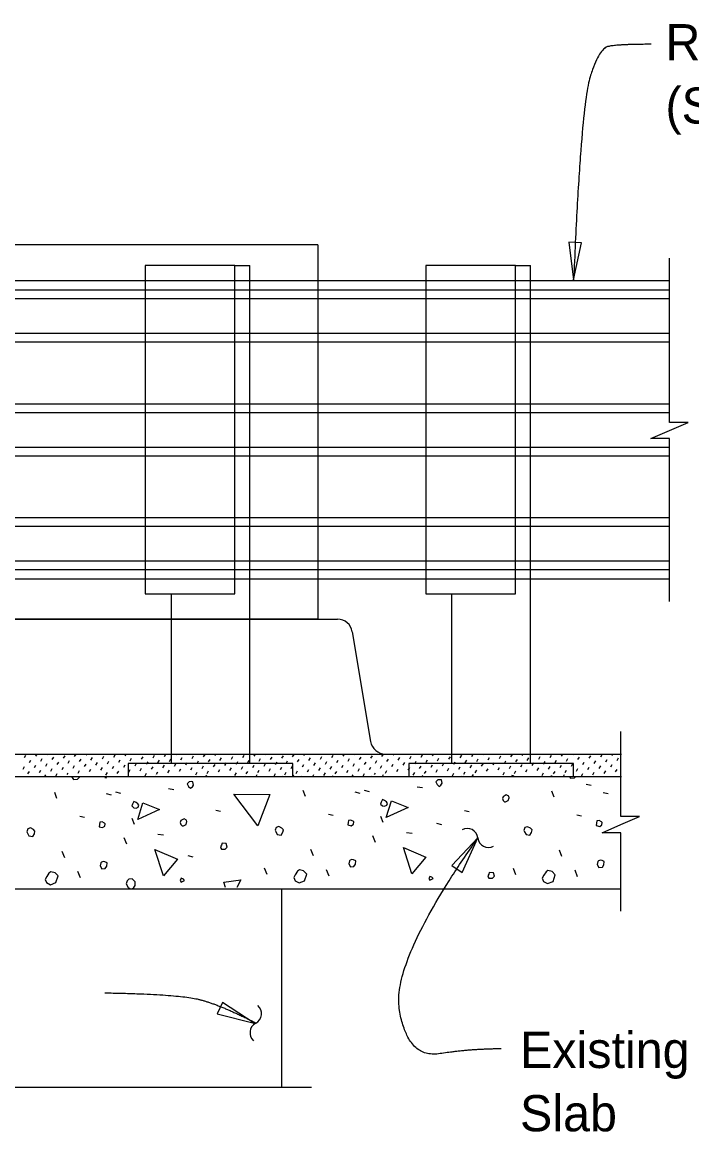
# Model space of a CAD drawing. Extents: x 0 to 41.1, y 0 to 25.9.
# Drawn here: x 16.72 to 20.45, y 6.25 to 12.42 of the extents above; entities that cross this region are included whole.
import ezdxf

# ---------------------------------------------------------------- set-up
doc = ezdxf.new("R2010")
doc.units = 0
for name, color, linetype in [('Dimension', 7, 'Continuous'), ('Miscellaneous', 7, 'Continuous'), ('TrafBarrierConc', 7, 'Continuous')]:
    doc.layers.add(name, color=color, linetype=linetype)

msp = doc.modelspace()

# ---------------------------------------------------------------- linework, layer by layer
at = {"layer": 'Dimension'}
for points in [[(19.789, 10.9864), (19.8331, 11.193), (19.7626, 11.196)], [(19.2567, 7.882), (19.1108, 7.7292), (19.1693, 7.6897)], [(18.0103, 6.8509), (17.8341, 6.9674), (17.8055, 6.9029)]]:
    msp.add_lwpolyline(points, close=True, dxfattribs=at)
for points in [[(20.3226, 9.1983), (20.3226, 10.1038), (20.2193, 10.1038), (20.3226, 10.1488), (20.426, 10.1938), (20.3226, 10.1938), (20.3226, 11.1084)], [(20.0523, 7.4738), (20.0523, 7.9111), (19.9489, 7.9111), (20.0523, 7.9561), (20.1556, 8.0011), (20.0523, 8.0011), (20.0523, 8.4739)], [(18.3306, 6.4942), (16.3423, 6.4942), (16.3423, 6.3779), (16.243, 6.6029), (16.243, 6.4942), (14.7437, 6.4942)]]:
    msp.add_lwpolyline(points, dxfattribs=at)
for centre, start, end in [((19.1968, 7.8756), 6.49806, 118.22528), ((19.3153, 7.8891), 186.49806, 298.22528), ((17.9922, 6.9044), 297.39149, 49.11871), ((18.047, 6.7985), 117.39149, 229.11871)]:
    msp.add_arc(centre, 0.0596, start, end, dxfattribs=at)
for points in [[(20.2213, 12.2973), (20.0218, 12.2973), (19.9303, 12.2696), (19.8306, 11.9592), (19.789, 10.9864)], [(19.3858, 6.7084), (19.2176, 6.7084), (18.8649, 6.655), (18.774, 7.1974), (19.2561, 7.8825)], [(17.1798, 7.0204), (17.5907, 7.013), (17.8234, 6.9532), (18.0193, 6.8535)]]:
    msp.add_open_spline(points, degree=2, dxfattribs=at)
at = {"layer": 'Miscellaneous'}
for p, q in [((17.9041, 11.0667), (17.9874, 11.0667)), ((17.9873, 8.2968), (17.9873, 11.0667)), ((19.4661, 11.0667), (19.5493, 11.0667)), ((19.5493, 8.2968), (19.5493, 11.0667)), ((11.0597, 10.9834), (20.3226, 10.9834)), ((11.7173, 10.9312), (20.3226, 10.9312)), ((11.7186, 10.8829), (20.3226, 10.8829)), ((11.7232, 10.6901), (20.3226, 10.6901)), ((11.7244, 10.6419), (20.3226, 10.6419)), ((11.7197, 10.2497), (20.3226, 10.2497)), ((11.721, 10.2979), (20.3226, 10.2979)), ((11.7103, 10.0088), (20.3226, 10.0088)), ((11.7145, 10.0569), (20.3226, 10.0569)), ((11.7244, 9.6648), (20.3226, 9.6648)), ((11.7232, 9.6166), (20.3226, 9.6166)), ((11.717, 9.4238), (20.3226, 9.4238)), ((11.0597, 9.3233), (20.3226, 9.3233)), ((11.718, 9.3755), (20.3226, 9.3755)), ((17.55, 8.2968), (17.55, 9.2399)), ((19.112, 8.2968), (19.112, 9.2399)), ((16.7325, 8.3291), (16.7406, 8.3431)), ((16.7959, 8.3372), (16.8027, 8.3489)), ((16.8594, 8.3453), (16.8615, 8.3489)), ((16.9506, 8.3257), (16.9587, 8.3397)), ((17.0115, 8.3345), (17.0196, 8.3485)), ((17.075, 8.3426), (17.0787, 8.3489)), ((17.1662, 8.323), (17.1743, 8.337)), ((17.2297, 8.3311), (17.2378, 8.3451)), ((17.2932, 8.3392), (17.2988, 8.3489)), ((17.3567, 8.3473), (17.3576, 8.3489)), ((17.4479, 8.3277), (17.456, 8.3417)), ((17.5114, 8.3358), (17.5189, 8.3489)), ((17.5749, 8.344), (17.5777, 8.3489)), ((17.6661, 8.3244), (17.6742, 8.3384)), ((17.7295, 8.3325), (17.7376, 8.3465)), ((17.793, 8.3406), (17.7979, 8.3489)), ((17.8565, 8.3487), (17.8567, 8.3489)), ((17.8842, 8.321), (17.8923, 8.335)), ((17.9477, 8.3291), (17.9558, 8.3431)), ((18.0112, 8.3372), (18.018, 8.3489)), ((18.0747, 8.3453), (18.0768, 8.3489)), ((18.1659, 8.3257), (18.174, 8.3397)), ((18.2248, 8.3325), (18.2329, 8.3465)), ((18.2883, 8.3406), (18.2931, 8.3489)), ((18.3518, 8.3487), (18.3519, 8.3489)), ((18.3795, 8.321), (18.3876, 8.335)), ((18.443, 8.3291), (18.4511, 8.3431)), ((18.5065, 8.3372), (18.5133, 8.3489)), ((18.57, 8.3453), (18.5721, 8.3489)), ((18.6612, 8.3257), (18.6693, 8.3397)), ((18.7221, 8.3345), (18.7302, 8.3485)), ((18.7856, 8.3426), (18.7892, 8.3489)), ((18.8767, 8.323), (18.8848, 8.337)), ((18.9402, 8.3311), (18.9483, 8.3451)), ((19.0037, 8.3392), (19.0093, 8.3489)), ((19.0672, 8.3473), (19.0681, 8.3489)), ((19.1584, 8.3277), (19.1665, 8.3417)), ((19.2219, 8.3358), (19.2295, 8.3489)), ((19.2854, 8.344), (19.2883, 8.3489)), ((19.3766, 8.3244), (19.3847, 8.3384)), ((19.4401, 8.3325), (19.4482, 8.3465)), ((19.5036, 8.3406), (19.5084, 8.3489)), ((19.5671, 8.3487), (19.5672, 8.3489)), ((19.5947, 8.321), (19.6028, 8.335)), ((19.6582, 8.3291), (19.6663, 8.3431)), ((19.7217, 8.3372), (19.7285, 8.3489)), ((19.7852, 8.3453), (19.7873, 8.3489)), ((19.8764, 8.3257), (19.8845, 8.3397)), ((19.94, 8.3325), (19.9481, 8.3465)), ((20.0035, 8.3406), (20.0083, 8.3489)), ((16.7244, 8.2656), (16.7325, 8.2796)), ((16.7602, 8.3014), (16.7683, 8.3154)), ((16.7878, 8.2737), (16.7959, 8.2877)), ((16.8236, 8.3095), (16.8317, 8.3235)), ((16.8513, 8.2818), (16.8594, 8.2958)), ((16.8871, 8.3176), (16.8952, 8.3316)), ((16.9148, 8.2899), (16.9229, 8.3039)), ((16.9425, 8.2622), (16.9506, 8.2762)), ((16.9757, 8.2987), (16.9838, 8.3127)), ((17.0034, 8.271), (17.0115, 8.285)), ((17.0392, 8.3068), (17.0473, 8.3208)), ((17.0669, 8.2791), (17.075, 8.2931)), ((17.1027, 8.3149), (17.1108, 8.3289)), ((17.1304, 8.2872), (17.1385, 8.3012)), ((17.1581, 8.2595), (17.1662, 8.2735)), ((17.1939, 8.2953), (17.202, 8.3093)), ((17.2216, 8.2676), (17.2297, 8.2816)), ((17.2574, 8.3034), (17.2655, 8.3174)), ((17.2851, 8.2757), (17.2932, 8.2897)), ((17.3209, 8.3115), (17.329, 8.3255)), ((17.3486, 8.2838), (17.3567, 8.2978)), ((17.3844, 8.3196), (17.3925, 8.3336)), ((17.4121, 8.2919), (17.4202, 8.3059)), ((17.4398, 8.2643), (17.4479, 8.2782)), ((17.4756, 8.3001), (17.4837, 8.314)), ((17.5033, 8.2724), (17.5114, 8.2864)), ((17.5391, 8.3082), (17.5472, 8.3221)), ((17.5668, 8.2805), (17.5749, 8.2945)), ((17.6026, 8.3163), (17.6107, 8.3303)), ((17.6303, 8.2886), (17.6384, 8.3026)), ((17.658, 8.2609), (17.6661, 8.2749)), ((17.6937, 8.2967), (17.7019, 8.3107)), ((17.7214, 8.269), (17.7295, 8.283)), ((17.7572, 8.3048), (17.7653, 8.3188)), ((17.7849, 8.2771), (17.793, 8.2911)), ((17.8207, 8.3129), (17.8288, 8.3269)), ((17.8484, 8.2852), (17.8565, 8.2992)), ((17.9119, 8.2933), (17.92, 8.3073)), ((17.9396, 8.2656), (17.9477, 8.2796)), ((17.9754, 8.3014), (17.9835, 8.3154)), ((18.0031, 8.2737), (18.0112, 8.2877)), ((18.0389, 8.3095), (18.047, 8.3235)), ((18.0666, 8.2818), (18.0747, 8.2958)), ((18.1024, 8.3176), (18.1105, 8.3316)), ((18.1301, 8.2899), (18.1382, 8.3039)), ((18.1578, 8.2622), (18.1659, 8.2762)), ((18.189, 8.2967), (18.1971, 8.3107)), ((18.2167, 8.269), (18.2248, 8.283)), ((18.2525, 8.3048), (18.2606, 8.3188)), ((18.2802, 8.2771), (18.2883, 8.2911)), ((18.316, 8.3129), (18.3241, 8.3269)), ((18.3437, 8.2852), (18.3518, 8.2992)), ((18.4072, 8.2933), (18.4153, 8.3073)), ((18.4349, 8.2656), (18.443, 8.2796)), ((18.4707, 8.3014), (18.4788, 8.3154)), ((18.4984, 8.2737), (18.5065, 8.2877)), ((18.5342, 8.3095), (18.5423, 8.3235)), ((18.5619, 8.2818), (18.57, 8.2958)), ((18.5977, 8.3176), (18.6058, 8.3316)), ((18.6254, 8.2899), (18.6335, 8.3039)), ((18.653, 8.2622), (18.6612, 8.2762)), ((18.6863, 8.2987), (18.6944, 8.3127)), ((18.714, 8.271), (18.7221, 8.285)), ((18.7498, 8.3068), (18.7579, 8.3208)), ((18.7774, 8.2791), (18.7856, 8.2931)), ((18.8132, 8.3149), (18.8213, 8.3289)), ((18.8409, 8.2872), (18.849, 8.3012)), ((18.8686, 8.2595), (18.8767, 8.2735)), ((18.9044, 8.2953), (18.9125, 8.3093)), ((18.9321, 8.2676), (18.9402, 8.2816)), ((18.9679, 8.3034), (18.976, 8.3174)), ((18.9956, 8.2757), (19.0037, 8.2897)), ((19.0314, 8.3115), (19.0395, 8.3255)), ((19.0591, 8.2838), (19.0672, 8.2978)), ((19.0949, 8.3196), (19.103, 8.3336)), ((19.1226, 8.2919), (19.1307, 8.3059)), ((19.1503, 8.2643), (19.1584, 8.2782)), ((19.1861, 8.3001), (19.1942, 8.314)), ((19.2138, 8.2724), (19.2219, 8.2864)), ((19.2496, 8.3082), (19.2577, 8.3221)), ((19.2773, 8.2805), (19.2854, 8.2945)), ((19.3131, 8.3163), (19.3212, 8.3303)), ((19.3408, 8.2886), (19.3489, 8.3026)), ((19.3685, 8.2609), (19.3766, 8.2749)), ((19.4043, 8.2967), (19.4124, 8.3107)), ((19.432, 8.269), (19.4401, 8.283)), ((19.4678, 8.3048), (19.4759, 8.3188)), ((19.4955, 8.2771), (19.5036, 8.2911)), ((19.5313, 8.3129), (19.5394, 8.3269)), ((19.5589, 8.2852), (19.5671, 8.2992)), ((19.6224, 8.2933), (19.6305, 8.3073)), ((19.6501, 8.2656), (19.6582, 8.2796)), ((19.6859, 8.3014), (19.694, 8.3154)), ((19.7136, 8.2737), (19.7217, 8.2877)), ((19.7494, 8.3095), (19.7575, 8.3235)), ((19.7771, 8.2818), (19.7852, 8.2958)), ((19.8129, 8.3176), (19.821, 8.3316)), ((19.8406, 8.2899), (19.8487, 8.3039)), ((19.8683, 8.2622), (19.8764, 8.2762)), ((19.9042, 8.2967), (19.9123, 8.3107)), ((19.9319, 8.269), (19.94, 8.283)), ((19.9677, 8.3048), (19.9758, 8.3188)), ((19.9954, 8.2771), (20.0035, 8.2911)), ((20.0312, 8.3129), (20.0393, 8.3269)), ((16.752, 8.2379), (16.7602, 8.2519)), ((16.7877, 8.2239), (16.7878, 8.2242)), ((16.8155, 8.246), (16.8236, 8.26)), ((16.8465, 8.2239), (16.8513, 8.2323)), ((16.879, 8.2541), (16.8871, 8.2681)), ((16.9067, 8.2264), (16.9148, 8.2404)), ((16.9702, 8.2345), (16.9753, 8.2432)), ((17.0311, 8.2433), (17.0392, 8.2573)), ((17.0946, 8.2514), (17.1027, 8.2654)), ((17.1858, 8.2318), (17.1939, 8.2458)), ((17.2493, 8.2399), (17.2574, 8.2539)), ((17.3128, 8.248), (17.3209, 8.262)), ((17.3763, 8.2562), (17.3844, 8.2701)), ((17.404, 8.2285), (17.4121, 8.2425)), ((17.4636, 8.2239), (17.4649, 8.2262)), ((17.4675, 8.2366), (17.4756, 8.2506)), ((17.531, 8.2447), (17.5391, 8.2587)), ((17.5945, 8.2528), (17.6026, 8.2668)), ((17.6856, 8.2332), (17.6937, 8.2472)), ((17.7425, 8.2239), (17.7466, 8.231)), ((17.7491, 8.2413), (17.7572, 8.2553)), ((17.8126, 8.2494), (17.8207, 8.2634)), ((17.8761, 8.2575), (17.8842, 8.2715)), ((17.9038, 8.2298), (17.9119, 8.2438)), ((17.9626, 8.2239), (17.9647, 8.2276)), ((17.9673, 8.2379), (17.9754, 8.2519)), ((18.0214, 8.2239), (18.0282, 8.2357)), ((18.0308, 8.246), (18.0389, 8.26)), ((18.0943, 8.2541), (18.1024, 8.2681)), ((18.122, 8.2264), (18.1301, 8.2404)), ((18.1673, 8.2239), (18.168, 8.2251)), ((18.1809, 8.2332), (18.189, 8.2472)), ((18.2261, 8.2239), (18.2315, 8.2332)), ((18.2444, 8.2413), (18.2525, 8.2553)), ((18.2781, 8.2239), (18.2802, 8.2276)), ((18.3079, 8.2494), (18.316, 8.2634)), ((18.3369, 8.2239), (18.3437, 8.2357)), ((18.3714, 8.2575), (18.3795, 8.2715)), ((18.3991, 8.2298), (18.4072, 8.2438)), ((18.4463, 8.2239), (18.4497, 8.2298)), ((18.4626, 8.2379), (18.4707, 8.2519)), ((18.4982, 8.2239), (18.4984, 8.2242)), ((18.5261, 8.246), (18.5342, 8.26)), ((18.557, 8.2239), (18.5619, 8.2323)), ((18.5896, 8.2541), (18.5977, 8.2681)), ((18.6173, 8.2264), (18.6254, 8.2404)), ((18.6664, 8.2239), (18.6678, 8.2264)), ((18.6807, 8.2345), (18.6858, 8.2432)), ((18.7252, 8.2239), (18.7313, 8.2345)), ((18.7417, 8.2433), (18.7498, 8.2573)), ((18.8051, 8.2514), (18.8132, 8.2654)), ((18.8963, 8.2318), (18.9044, 8.2458)), ((18.9453, 8.2239), (18.9495, 8.2311)), ((18.9598, 8.2399), (18.9679, 8.2539)), ((19.0233, 8.248), (19.0314, 8.262)), ((19.0868, 8.2562), (19.0949, 8.2701)), ((19.1145, 8.2285), (19.1226, 8.2425)), ((19.1655, 8.2239), (19.1677, 8.2277)), ((19.1741, 8.2239), (19.1754, 8.2262)), ((19.178, 8.2366), (19.1861, 8.2506)), ((19.2243, 8.2239), (19.2312, 8.2358)), ((19.2415, 8.2447), (19.2496, 8.2587)), ((19.305, 8.2528), (19.3131, 8.2668)), ((19.3856, 8.2239), (19.3858, 8.2243)), ((19.3962, 8.2332), (19.4043, 8.2472)), ((19.4444, 8.2239), (19.4493, 8.2324)), ((19.453, 8.2239), (19.4571, 8.231)), ((19.4597, 8.2413), (19.4678, 8.2553)), ((19.5232, 8.2494), (19.5313, 8.2634)), ((19.5866, 8.2575), (19.5947, 8.2715)), ((19.6143, 8.2298), (19.6224, 8.2438)), ((19.6645, 8.2239), (19.6675, 8.229)), ((19.6731, 8.2239), (19.6753, 8.2276)), ((19.6778, 8.2379), (19.6859, 8.2519)), ((19.7319, 8.2239), (19.7388, 8.2357)), ((19.7413, 8.246), (19.7494, 8.26)), ((19.8048, 8.2541), (19.8129, 8.2681)), ((19.8325, 8.2264), (19.8406, 8.2404)), ((19.8855, 8.2239), (19.8858, 8.2243)), ((19.8961, 8.2332), (19.9042, 8.2472)), ((19.9596, 8.2413), (19.9677, 8.2553)), ((20.0231, 8.2494), (20.0312, 8.2634)), ((17.5344, 8.1567), (17.5644, 8.1514)), ((18.9181, 8.1673), (18.9481, 8.162)), ((19.8587, 8.182), (19.887, 8.175)), ((16.913, 8.1019), (16.9006, 8.1355)), ((17.187, 8.1285), (17.2153, 8.1214)), ((17.2387, 8.1377), (17.267, 8.1307)), ((18.2967, 8.1125), (18.2843, 8.1461)), ((18.5707, 8.1391), (18.599, 8.132)), ((18.6224, 8.1483), (18.6507, 8.1413)), ((19.68, 8.109), (19.6676, 8.1426)), ((19.954, 8.1355), (19.9823, 8.1285)), ((17.7968, 8.0359), (17.8234, 8.0306)), ((19.1815, 8.0348), (19.208, 8.0295)), ((17.0403, 8.0029), (17.0668, 7.9976)), ((17.3448, 7.9565), (17.3324, 7.9901)), ((18.424, 8.0136), (18.4505, 8.0082)), ((18.7285, 7.9671), (18.7161, 8.0007)), ((19.0259, 7.964), (19.0542, 7.9569)), ((19.8072, 8.01), (19.8338, 8.0047)), ((17.4743, 7.9022), (17.5061, 7.8986)), ((18.858, 7.9128), (18.8898, 7.9093)), ((17.3023, 7.8469), (17.2882, 7.8823)), ((18.686, 7.8575), (18.6719, 7.8929)), ((16.9572, 7.7714), (16.943, 7.8067)), ((17.6422, 7.7837), (17.6705, 7.7767)), ((18.3409, 7.782), (18.3267, 7.8173)), ((19.7242, 7.7784), (19.71, 7.8138)), ((17.0442, 7.6596), (17.0301, 7.6949)), ((18.0832, 7.6788), (18.0691, 7.7142)), ((18.4279, 7.6702), (18.4138, 7.7055)), ((19.4678, 7.6777), (19.4537, 7.713)), ((19.8112, 7.6666), (19.7971, 7.702))]:
    msp.add_line(p, q, dxfattribs=at)
for points in [[(17.4041, 9.24), (17.9041, 9.24), (17.9041, 11.0667), (17.4041, 11.0667)], [(18.9661, 9.24), (19.4661, 9.24), (19.4661, 11.0667), (18.9661, 11.0667)], [(17.3104, 8.2239), (18.227, 8.2239), (18.227, 8.2968), (17.3104, 8.2968)], [(18.8724, 8.2239), (19.789, 8.2239), (19.789, 8.2968), (18.8724, 8.2968)]]:
    msp.add_lwpolyline(points, close=True, dxfattribs=at)
for points in [[(16.9951, 8.2238), (17.0049, 8.208), (17.0279, 8.2098), (17.0367, 8.2186), (17.042, 8.2238)], [(17.1839, 8.2138), (17.1807, 8.2238)], [(17.1891, 8.2238), (17.1839, 8.2138)], [(19.7665, 8.2238), (19.7719, 8.2151), (19.7949, 8.2168), (19.8019, 8.2238)], [(17.6457, 8.1691), (17.6563, 8.1585), (17.6669, 8.1656), (17.674, 8.1762), (17.6705, 8.1939), (17.6616, 8.1956), (17.6493, 8.1939), (17.6387, 8.1833), (17.6457, 8.1691)], [(19.0294, 8.1797), (19.04, 8.1691), (19.0506, 8.1762), (19.0577, 8.1868), (19.0542, 8.2045), (19.0453, 8.2062), (19.033, 8.2045), (19.0224, 8.1939), (19.0294, 8.1797)], [(18.032, 7.9493), (17.8976, 8.1261), (18.0974, 8.1243), (18.032, 7.9493)], [(18.7249, 8.06), (18.7373, 8.0582), (18.7497, 8.0635), (18.7532, 8.0741), (18.7479, 8.0829), (18.7373, 8.09), (18.7249, 8.0953), (18.7179, 8.0812), (18.7143, 8.0706), (18.7249, 8.06)], [(18.7466, 7.9959), (18.7749, 8.0878), (18.8686, 8.0507), (18.7466, 7.9959)], [(19.4035, 8.0831), (19.4106, 8.0831), (19.4247, 8.0902), (19.43, 8.1061), (19.4283, 8.1149), (19.4141, 8.122), (19.3964, 8.1114), (19.3929, 8.1008), (19.3964, 8.0902), (19.4035, 8.0831)], [(17.3412, 8.0494), (17.3536, 8.0476), (17.366, 8.0529), (17.3695, 8.0635), (17.3642, 8.0723), (17.3536, 8.0794), (17.3412, 8.0847), (17.3342, 8.0706), (17.3306, 8.06), (17.3412, 8.0494)], [(17.3629, 7.9853), (17.3912, 8.0772), (17.4849, 8.0401), (17.3629, 7.9853)], [(17.1481, 7.9446), (17.1676, 7.9393), (17.1799, 7.9481), (17.1817, 7.9605), (17.1782, 7.9641), (17.164, 7.9711), (17.1516, 7.9694), (17.1499, 7.957), (17.1481, 7.9446)], [(17.6104, 7.9499), (17.6174, 7.9499), (17.6316, 7.957), (17.6369, 7.9729), (17.6351, 7.9817), (17.621, 7.9888), (17.6033, 7.9782), (17.5998, 7.9676), (17.6033, 7.957), (17.6104, 7.9499)], [(18.5318, 7.9552), (18.5512, 7.9499), (18.5636, 7.9588), (18.5654, 7.9711), (18.5618, 7.9747), (18.5477, 7.9817), (18.5353, 7.98), (18.5336, 7.9676), (18.5318, 7.9552)], [(19.9151, 7.9517), (19.9345, 7.9464), (19.9469, 7.9552), (19.9487, 7.9676), (19.9451, 7.9711), (19.931, 7.9782), (19.9186, 7.9764), (19.9168, 7.9641), (19.9151, 7.9517)], [(16.7486, 7.9093), (16.7574, 7.8933), (16.7786, 7.8898), (16.7875, 7.9057), (16.791, 7.9199), (16.7822, 7.9287), (16.7663, 7.9375), (16.7504, 7.9322), (16.7451, 7.9163), (16.7486, 7.9093)], [(18.1309, 7.9175), (18.1398, 7.9016), (18.161, 7.898), (18.1698, 7.9139), (18.1734, 7.9281), (18.1645, 7.9369), (18.1486, 7.9457), (18.1327, 7.9404), (18.1274, 7.9245), (18.1309, 7.9175)], [(19.5156, 7.9163), (19.5244, 7.9004), (19.5456, 7.8969), (19.5545, 7.9128), (19.558, 7.9269), (19.5491, 7.9358), (19.5332, 7.9446), (19.5173, 7.9393), (19.512, 7.9234), (19.5156, 7.9163)], [(17.8287, 7.8202), (17.8499, 7.8202), (17.8605, 7.8308), (17.8552, 7.8503), (17.8322, 7.8521), (17.8287, 7.8414), (17.8234, 7.8326), (17.8287, 7.8202), (17.8251, 7.8238)], [(17.5056, 7.6719), (17.4579, 7.8187), (17.5834, 7.7639), (17.5056, 7.6719)], [(18.8893, 7.6825), (18.8416, 7.8293), (18.9671, 7.7745), (18.8893, 7.6825)], [(17.1539, 7.7267), (17.1627, 7.7108), (17.1821, 7.7126), (17.191, 7.725), (17.1927, 7.7444), (17.1804, 7.7497), (17.1715, 7.7515), (17.1609, 7.7479), (17.1574, 7.7444), (17.1539, 7.7267)], [(18.5375, 7.7373), (18.5464, 7.7214), (18.5658, 7.7232), (18.5747, 7.7356), (18.5764, 7.755), (18.5641, 7.7603), (18.5552, 7.7621), (18.5446, 7.7586), (18.5411, 7.755), (18.5375, 7.7373)], [(19.9208, 7.7338), (19.9297, 7.7179), (19.9491, 7.7197), (19.9579, 7.732), (19.9597, 7.7515), (19.9473, 7.7568), (19.9385, 7.7586), (19.9279, 7.755), (19.9244, 7.7515), (19.9208, 7.7338)], [(16.8547, 7.6335), (16.8776, 7.6211), (16.9077, 7.6335), (16.9201, 7.6706), (16.9024, 7.6883), (16.8794, 7.6936), (16.8688, 7.6865), (16.8564, 7.6671), (16.8476, 7.6512), (16.8547, 7.6335)], [(17.6046, 7.6366), (17.6241, 7.6454), (17.617, 7.6525), (17.6046, 7.6578), (17.5993, 7.6454), (17.6046, 7.6366)], [(18.2383, 7.6441), (18.2613, 7.6317), (18.2914, 7.6441), (18.3038, 7.6812), (18.2861, 7.6989), (18.2631, 7.7042), (18.2525, 7.6971), (18.2401, 7.6777), (18.2313, 7.6618), (18.2383, 7.6441)], [(18.9883, 7.6472), (19.0078, 7.656), (19.0007, 7.6631), (18.9883, 7.6684), (18.983, 7.656), (18.9883, 7.6472)], [(19.3163, 7.6585), (19.3375, 7.6585), (19.3481, 7.6691), (19.3428, 7.6886), (19.3198, 7.6903), (19.3163, 7.6797), (19.311, 7.6709), (19.3163, 7.6585), (19.3128, 7.662)], [(19.6216, 7.6406), (19.6446, 7.6282), (19.6747, 7.6406), (19.687, 7.6777), (19.6694, 7.6954), (19.6464, 7.7007), (19.6358, 7.6936), (19.6234, 7.6741), (19.6146, 7.6582), (19.6216, 7.6406)], [(17.331, 7.5989), (17.3412, 7.6065), (17.3483, 7.6171), (17.3483, 7.6383), (17.3324, 7.6543), (17.3129, 7.6525), (17.3041, 7.6436), (17.2988, 7.6277)], [(17.2988, 7.6277), (17.3094, 7.6065), (17.3222, 7.5989)], [(17.8522, 7.6071), (17.8428, 7.6364), (17.9365, 7.6488), (17.915, 7.6071)]]:
    msp.add_lwpolyline(points, dxfattribs=at)
at = {"layer": 'TrafBarrierConc'}
for p, q in [((18.3647, 11.1822), (8.3411, 11.1822)), ((18.3647, 11.1822), (18.3647, 9.0989)), ((18.3647, 9.0989), (8.3411, 9.0989)), ((12.1382, 9.0989), (18.4751, 9.0989)), ((18.5573, 9.0293), (18.6591, 8.4185)), ((8.3411, 8.3489), (20.0548, 8.3489)), ((10.3412, 8.2239), (20.0548, 8.2239)), ((13.561, 7.5988), (20.0547, 7.5988)), ((18.1623, 7.5988), (18.1623, 6.4941))]:
    msp.add_line(p, q, dxfattribs=at)
for centre, start, end in [((18.4751, 9.0156), 9.46297, 90), ((18.7413, 8.4322), 189.46297, 270)]:
    msp.add_arc(centre, 0.0833, start, end, dxfattribs=at)

# ---------------------------------------------------------------- texts
at = {"layer": 'Dimension'}
for s, p in [('Roadway Guardrail Transition', (20.3003, 12.208)), ('(See Note 1, This Sheet & Note 1, Sheet 1)', (20.3003, 11.856)), ('Existing Approach ', (19.4908, 6.6021)), ('Slab', (19.4908, 6.2501))]:
    msp.add_text(s, height=0.2016, dxfattribs=at).set_placement(p)

doc.saveas('drawing.dxf')
